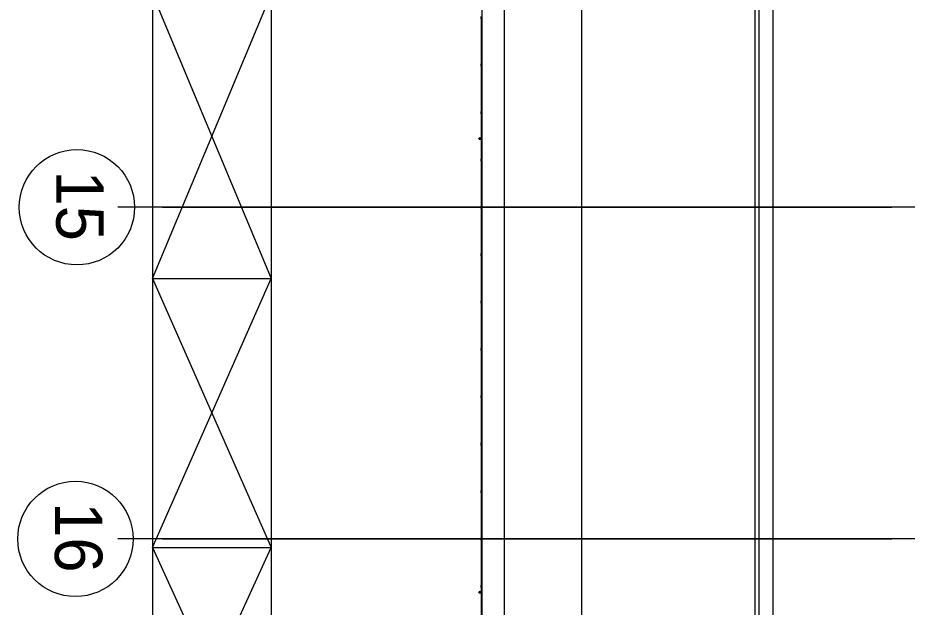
# Model space of a CAD drawing. Extents: x -264165 to -263575, y -1242333 to -1242036.
# Drawn here: x -263923.93 to -263905.18, y -1242183.32 to -1242170.88 of the extents above; entities that cross this region are included whole.
import ezdxf

# ---------------------------------------------------------------- set-up
doc = ezdxf.new("R2010")
doc.units = 0
doc.layers.add('KFA_HESCON_OSI_STAVBY', color=7, linetype='Continuous')
doc.layers.add('KFA_SITUACIA_DRS_VYTYCOVAK_SEDA', color=7, linetype='Continuous')

msp = doc.modelspace()

# ---------------------------------------------------------------- linework, layer by layer
at = {"layer": 'KFA_HESCON_OSI_STAVBY'}
for p, q in [((-263908.393, -1242080.447), (-263908.393, -1242248.737)), ((-263787.486, -1242174.882), (-263921.823, -1242174.882)), ((-263920.885, -1242174.882), (-263905.505, -1242174.882)), ((-263787.486, -1242181.882), (-263921.823, -1242181.882)), ((-263920.885, -1242181.882), (-263905.505, -1242181.882))]:
    msp.add_line(p, q, dxfattribs=at)
for centre in [(-263922.688, -1242174.882), (-263922.718, -1242181.882)]:
    msp.add_circle(centre, 1.216, dxfattribs=at)
at = {"layer": 'KFA_SITUACIA_DRS_VYTYCOVAK_SEDA'}
for p, q in [((-263921.093, -1242087.308), (-263921.093, -1242241.458)), ((-263912.043, -1242228.625), (-263912.043, -1242100.14)), ((-263914.153, -1242132.422), (-263914.153, -1242196.342)), ((-263914.153, -1242132.422), (-263914.153, -1242196.342)), ((-263914.143, -1242196.333), (-263914.143, -1242132.433)), ((-263913.683, -1242132.892), (-263913.683, -1242195.872)), ((-263913.683, -1242132.892), (-263913.683, -1242195.872)), ((-263908.308, -1242135.882), (-263908.308, -1242192.882)), ((-263908.308, -1242135.882), (-263908.308, -1242192.882)), ((-263908.008, -1242192.882), (-263908.008, -1242135.882)), ((-263908.008, -1242192.882), (-263908.008, -1242135.882)), ((-263918.593, -1242141.207), (-263918.593, -1242187.557)), ((-263921.093, -1242170.382), (-263918.593, -1242176.382)), ((-263921.093, -1242176.382), (-263918.593, -1242170.382)), ((-263914.168, -1242170.907), (-263914.168, -1242170.857)), ((-263914.168, -1242170.907), (-263914.168, -1242170.857)), ((-263914.168, -1242170.907), (-263914.168, -1242171.857)), ((-263914.168, -1242170.907), (-263914.168, -1242171.857)), ((-263914.168, -1242170.907), (-263914.168, -1242171.857)), ((-263914.168, -1242170.907), (-263914.168, -1242171.857)), ((-263914.168, -1242171.907), (-263914.168, -1242171.857)), ((-263914.168, -1242171.907), (-263914.168, -1242171.857)), ((-263914.168, -1242171.907), (-263914.168, -1242172.857)), ((-263914.168, -1242171.907), (-263914.168, -1242172.857)), ((-263914.168, -1242171.907), (-263914.168, -1242172.857)), ((-263914.168, -1242171.907), (-263914.168, -1242172.857)), ((-263914.168, -1242172.907), (-263914.168, -1242172.857)), ((-263914.168, -1242172.907), (-263914.168, -1242172.857)), ((-263914.168, -1242172.907), (-263914.168, -1242173.857)), ((-263914.168, -1242172.907), (-263914.168, -1242173.857)), ((-263914.213, -1242173.432), (-263914.21, -1242173.422)), ((-263914.213, -1242173.432), (-263914.21, -1242173.422)), ((-263914.21, -1242173.442), (-263914.213, -1242173.432)), ((-263914.21, -1242173.442), (-263914.213, -1242173.432)), ((-263914.21, -1242173.422), (-263914.203, -1242173.415)), ((-263914.21, -1242173.422), (-263914.203, -1242173.415)), ((-263914.21, -1242173.424), (-263914.21, -1242173.422)), ((-263914.21, -1242173.424), (-263914.21, -1242173.422)), ((-263914.21, -1242173.427), (-263914.21, -1242173.424)), ((-263914.21, -1242173.427), (-263914.21, -1242173.424)), ((-263914.21, -1242173.432), (-263914.21, -1242173.427)), ((-263914.21, -1242173.432), (-263914.21, -1242173.427)), ((-263914.21, -1242173.437), (-263914.21, -1242173.432)), ((-263914.21, -1242173.437), (-263914.21, -1242173.432)), ((-263914.21, -1242173.441), (-263914.21, -1242173.437)), ((-263914.21, -1242173.441), (-263914.21, -1242173.437)), ((-263914.21, -1242173.442), (-263914.21, -1242173.441)), ((-263914.21, -1242173.442), (-263914.21, -1242173.441)), ((-263914.203, -1242173.45), (-263914.21, -1242173.442)), ((-263914.203, -1242173.45), (-263914.21, -1242173.442)), ((-263914.203, -1242173.415), (-263914.193, -1242173.412)), ((-263914.203, -1242173.415), (-263914.193, -1242173.412)), ((-263914.203, -1242173.417), (-263914.203, -1242173.415)), ((-263914.203, -1242173.417), (-263914.203, -1242173.415)), ((-263914.203, -1242173.417), (-263914.193, -1242173.415)), ((-263914.203, -1242173.417), (-263914.193, -1242173.415)), ((-263914.203, -1242173.424), (-263914.203, -1242173.417)), ((-263914.203, -1242173.424), (-263914.203, -1242173.417)), ((-263914.203, -1242173.424), (-263914.193, -1242173.422)), ((-263914.203, -1242173.424), (-263914.193, -1242173.422)), ((-263914.203, -1242173.432), (-263914.203, -1242173.424)), ((-263914.203, -1242173.432), (-263914.203, -1242173.424)), ((-263914.203, -1242173.441), (-263914.203, -1242173.432)), ((-263914.203, -1242173.441), (-263914.203, -1242173.432)), ((-263914.203, -1242173.432), (-263914.193, -1242173.432)), ((-263914.203, -1242173.432), (-263914.193, -1242173.432)), ((-263914.203, -1242173.441), (-263914.193, -1242173.442)), ((-263914.203, -1242173.441), (-263914.193, -1242173.442)), ((-263914.203, -1242173.447), (-263914.203, -1242173.441)), ((-263914.203, -1242173.447), (-263914.203, -1242173.441)), ((-263914.203, -1242173.45), (-263914.203, -1242173.447)), ((-263914.203, -1242173.45), (-263914.203, -1242173.447)), ((-263914.203, -1242173.447), (-263914.193, -1242173.45)), ((-263914.203, -1242173.447), (-263914.193, -1242173.45)), ((-263914.193, -1242173.452), (-263914.203, -1242173.45)), ((-263914.193, -1242173.452), (-263914.203, -1242173.45)), ((-263914.193, -1242173.412), (-263914.183, -1242173.415)), ((-263914.193, -1242173.412), (-263914.183, -1242173.415)), ((-263914.193, -1242173.412), (-263914.193, -1242173.415)), ((-263914.193, -1242173.412), (-263914.193, -1242173.415)), ((-263914.193, -1242173.415), (-263914.183, -1242173.417)), ((-263914.193, -1242173.415), (-263914.183, -1242173.417)), ((-263914.193, -1242173.415), (-263914.193, -1242173.422)), ((-263914.193, -1242173.415), (-263914.193, -1242173.422)), ((-263914.193, -1242173.422), (-263914.193, -1242173.432)), ((-263914.193, -1242173.422), (-263914.193, -1242173.432)), ((-263914.193, -1242173.422), (-263914.183, -1242173.424)), ((-263914.193, -1242173.422), (-263914.183, -1242173.424)), ((-263914.193, -1242173.432), (-263914.193, -1242173.442)), ((-263914.193, -1242173.432), (-263914.193, -1242173.442)), ((-263914.193, -1242173.432), (-263914.183, -1242173.432)), ((-263914.193, -1242173.432), (-263914.183, -1242173.432)), ((-263914.193, -1242173.442), (-263914.183, -1242173.441)), ((-263914.193, -1242173.442), (-263914.183, -1242173.441)), ((-263914.193, -1242173.442), (-263914.193, -1242173.45)), ((-263914.193, -1242173.442), (-263914.193, -1242173.45)), ((-263914.193, -1242173.45), (-263914.183, -1242173.447)), ((-263914.193, -1242173.45), (-263914.183, -1242173.447)), ((-263914.193, -1242173.45), (-263914.193, -1242173.452)), ((-263914.193, -1242173.45), (-263914.193, -1242173.452)), ((-263914.183, -1242173.45), (-263914.193, -1242173.452)), ((-263914.183, -1242173.45), (-263914.193, -1242173.452)), ((-263914.183, -1242173.415), (-263914.176, -1242173.422)), ((-263914.183, -1242173.415), (-263914.176, -1242173.422)), ((-263914.183, -1242173.415), (-263914.183, -1242173.417)), ((-263914.183, -1242173.415), (-263914.183, -1242173.417)), ((-263914.183, -1242173.417), (-263914.183, -1242173.424)), ((-263914.183, -1242173.417), (-263914.183, -1242173.424)), ((-263914.183, -1242173.424), (-263914.183, -1242173.432)), ((-263914.183, -1242173.424), (-263914.183, -1242173.432)), ((-263914.183, -1242173.432), (-263914.183, -1242173.441)), ((-263914.183, -1242173.432), (-263914.183, -1242173.441)), ((-263914.183, -1242173.441), (-263914.183, -1242173.447)), ((-263914.183, -1242173.441), (-263914.183, -1242173.447)), ((-263914.176, -1242173.442), (-263914.183, -1242173.45)), ((-263914.176, -1242173.442), (-263914.183, -1242173.45)), ((-263914.183, -1242173.447), (-263914.183, -1242173.45)), ((-263914.183, -1242173.447), (-263914.183, -1242173.45)), ((-263914.176, -1242173.422), (-263914.168, -1242173.422)), ((-263914.176, -1242173.422), (-263914.168, -1242173.422)), ((-263914.176, -1242173.422), (-263914.176, -1242173.424)), ((-263914.176, -1242173.422), (-263914.176, -1242173.424)), ((-263914.176, -1242173.424), (-263914.168, -1242173.424)), ((-263914.176, -1242173.424), (-263914.168, -1242173.424)), ((-263914.176, -1242173.424), (-263914.176, -1242173.427)), ((-263914.176, -1242173.424), (-263914.176, -1242173.427)), ((-263914.176, -1242173.427), (-263914.168, -1242173.427)), ((-263914.176, -1242173.427), (-263914.168, -1242173.427)), ((-263914.176, -1242173.427), (-263914.176, -1242173.432)), ((-263914.176, -1242173.427), (-263914.176, -1242173.432)), ((-263914.176, -1242173.432), (-263914.168, -1242173.432)), ((-263914.176, -1242173.432), (-263914.168, -1242173.432)), ((-263914.176, -1242173.432), (-263914.176, -1242173.437)), ((-263914.176, -1242173.432), (-263914.176, -1242173.437)), ((-263914.176, -1242173.437), (-263914.168, -1242173.437)), ((-263914.176, -1242173.437), (-263914.168, -1242173.437)), ((-263914.176, -1242173.437), (-263914.176, -1242173.441)), ((-263914.176, -1242173.437), (-263914.176, -1242173.441)), ((-263914.176, -1242173.441), (-263914.168, -1242173.441)), ((-263914.176, -1242173.441), (-263914.168, -1242173.441)), ((-263914.176, -1242173.441), (-263914.176, -1242173.442)), ((-263914.176, -1242173.441), (-263914.176, -1242173.442)), ((-263914.176, -1242173.442), (-263914.168, -1242173.442)), ((-263914.176, -1242173.442), (-263914.168, -1242173.442)), ((-263914.168, -1242173.907), (-263914.168, -1242173.857)), ((-263914.168, -1242173.907), (-263914.168, -1242173.857)), ((-263914.168, -1242173.907), (-263914.168, -1242174.857)), ((-263914.168, -1242173.907), (-263914.168, -1242174.857)), ((-263914.168, -1242174.907), (-263914.168, -1242174.857)), ((-263914.168, -1242174.907), (-263914.168, -1242174.857)), ((-263914.168, -1242174.907), (-263914.168, -1242175.857)), ((-263914.168, -1242174.907), (-263914.168, -1242175.857)), ((-263914.168, -1242174.907), (-263914.168, -1242175.857)), ((-263914.168, -1242174.907), (-263914.168, -1242175.857)), ((-263914.168, -1242175.907), (-263914.168, -1242175.857)), ((-263914.168, -1242175.907), (-263914.168, -1242175.857)), ((-263914.168, -1242175.907), (-263914.168, -1242176.857)), ((-263914.168, -1242175.907), (-263914.168, -1242176.857)), ((-263914.168, -1242175.907), (-263914.168, -1242176.857)), ((-263914.168, -1242175.907), (-263914.168, -1242176.857)), ((-263921.093, -1242176.382), (-263918.593, -1242176.382)), ((-263921.093, -1242176.382), (-263918.593, -1242182.062)), ((-263921.093, -1242182.062), (-263918.593, -1242176.382)), ((-263914.168, -1242176.907), (-263914.168, -1242176.857)), ((-263914.168, -1242176.907), (-263914.168, -1242176.857)), ((-263914.168, -1242176.907), (-263914.168, -1242177.857)), ((-263914.168, -1242176.907), (-263914.168, -1242177.857)), ((-263914.168, -1242177.907), (-263914.168, -1242177.857)), ((-263914.168, -1242177.907), (-263914.168, -1242177.857)), ((-263914.168, -1242177.907), (-263914.168, -1242178.857)), ((-263914.168, -1242177.907), (-263914.168, -1242178.857)), ((-263914.168, -1242178.907), (-263914.168, -1242178.857)), ((-263914.168, -1242178.907), (-263914.168, -1242178.857)), ((-263914.168, -1242178.907), (-263914.168, -1242179.857)), ((-263914.168, -1242178.907), (-263914.168, -1242179.857)), ((-263914.168, -1242179.907), (-263914.168, -1242179.857)), ((-263914.168, -1242179.907), (-263914.168, -1242179.857)), ((-263914.168, -1242179.907), (-263914.168, -1242180.857)), ((-263914.168, -1242179.907), (-263914.168, -1242180.857)), ((-263914.168, -1242180.907), (-263914.168, -1242180.857)), ((-263914.168, -1242180.907), (-263914.168, -1242180.857)), ((-263914.168, -1242180.907), (-263914.168, -1242181.857)), ((-263914.168, -1242180.907), (-263914.168, -1242181.857)), ((-263914.168, -1242181.907), (-263914.168, -1242181.857)), ((-263914.168, -1242181.907), (-263914.168, -1242181.857)), ((-263914.168, -1242181.907), (-263914.168, -1242182.857)), ((-263914.168, -1242181.907), (-263914.168, -1242182.857)), ((-263921.093, -1242182.062), (-263918.593, -1242182.062)), ((-263921.093, -1242182.062), (-263918.593, -1242187.557)), ((-263921.093, -1242187.557), (-263918.593, -1242182.062)), ((-263914.168, -1242182.907), (-263914.168, -1242182.857)), ((-263914.168, -1242182.907), (-263914.168, -1242182.857)), ((-263914.213, -1242183.007), (-263914.21, -1242182.997)), ((-263914.213, -1242183.007), (-263914.21, -1242182.997)), ((-263914.21, -1242183.017), (-263914.213, -1242183.007)), ((-263914.21, -1242183.017), (-263914.213, -1242183.007)), ((-263914.21, -1242182.997), (-263914.203, -1242182.989)), ((-263914.21, -1242182.997), (-263914.203, -1242182.989)), ((-263914.21, -1242182.998), (-263914.21, -1242182.997)), ((-263914.21, -1242182.998), (-263914.21, -1242182.997)), ((-263914.21, -1242183.002), (-263914.21, -1242182.998)), ((-263914.21, -1242183.002), (-263914.21, -1242182.998)), ((-263914.21, -1242183.007), (-263914.21, -1242183.002)), ((-263914.21, -1242183.007), (-263914.21, -1242183.002)), ((-263914.21, -1242183.012), (-263914.21, -1242183.007)), ((-263914.21, -1242183.012), (-263914.21, -1242183.007)), ((-263914.21, -1242183.015), (-263914.21, -1242183.012)), ((-263914.21, -1242183.015), (-263914.21, -1242183.012)), ((-263914.21, -1242183.017), (-263914.21, -1242183.015)), ((-263914.21, -1242183.017), (-263914.21, -1242183.015)), ((-263914.203, -1242183.024), (-263914.21, -1242183.017)), ((-263914.203, -1242183.024), (-263914.21, -1242183.017)), ((-263914.203, -1242182.989), (-263914.193, -1242182.987)), ((-263914.203, -1242182.989), (-263914.193, -1242182.987)), ((-263914.203, -1242182.992), (-263914.203, -1242182.989)), ((-263914.203, -1242182.992), (-263914.203, -1242182.989)), ((-263914.203, -1242182.992), (-263914.193, -1242182.989)), ((-263914.203, -1242182.992), (-263914.193, -1242182.989)), ((-263914.203, -1242182.998), (-263914.203, -1242182.992)), ((-263914.203, -1242182.998), (-263914.203, -1242182.992)), ((-263914.203, -1242182.998), (-263914.193, -1242182.997)), ((-263914.203, -1242182.998), (-263914.193, -1242182.997)), ((-263914.203, -1242183.007), (-263914.203, -1242182.998)), ((-263914.203, -1242183.007), (-263914.203, -1242182.998)), ((-263914.203, -1242183.015), (-263914.203, -1242183.007)), ((-263914.203, -1242183.015), (-263914.203, -1242183.007)), ((-263914.203, -1242183.007), (-263914.193, -1242183.007)), ((-263914.203, -1242183.007), (-263914.193, -1242183.007)), ((-263914.203, -1242183.015), (-263914.193, -1242183.017)), ((-263914.203, -1242183.015), (-263914.193, -1242183.017)), ((-263914.203, -1242183.022), (-263914.203, -1242183.015)), ((-263914.203, -1242183.022), (-263914.203, -1242183.015)), ((-263914.203, -1242183.024), (-263914.203, -1242183.022)), ((-263914.203, -1242183.024), (-263914.203, -1242183.022)), ((-263914.203, -1242183.022), (-263914.193, -1242183.024)), ((-263914.203, -1242183.022), (-263914.193, -1242183.024)), ((-263914.193, -1242183.027), (-263914.203, -1242183.024)), ((-263914.193, -1242183.027), (-263914.203, -1242183.024)), ((-263914.193, -1242182.987), (-263914.183, -1242182.989)), ((-263914.193, -1242182.987), (-263914.183, -1242182.989)), ((-263914.193, -1242182.987), (-263914.193, -1242182.989)), ((-263914.193, -1242182.987), (-263914.193, -1242182.989)), ((-263914.193, -1242182.989), (-263914.183, -1242182.992)), ((-263914.193, -1242182.989), (-263914.183, -1242182.992)), ((-263914.193, -1242182.989), (-263914.193, -1242182.997)), ((-263914.193, -1242182.989), (-263914.193, -1242182.997)), ((-263914.193, -1242182.997), (-263914.193, -1242183.007)), ((-263914.193, -1242182.997), (-263914.193, -1242183.007)), ((-263914.193, -1242182.997), (-263914.183, -1242182.998)), ((-263914.193, -1242182.997), (-263914.183, -1242182.998)), ((-263914.193, -1242183.007), (-263914.193, -1242183.017)), ((-263914.193, -1242183.007), (-263914.193, -1242183.017)), ((-263914.193, -1242183.007), (-263914.183, -1242183.007)), ((-263914.193, -1242183.007), (-263914.183, -1242183.007)), ((-263914.193, -1242183.017), (-263914.183, -1242183.015)), ((-263914.193, -1242183.017), (-263914.183, -1242183.015)), ((-263914.193, -1242183.017), (-263914.193, -1242183.024)), ((-263914.193, -1242183.017), (-263914.193, -1242183.024)), ((-263914.193, -1242183.024), (-263914.183, -1242183.022)), ((-263914.193, -1242183.024), (-263914.183, -1242183.022)), ((-263914.193, -1242183.024), (-263914.193, -1242183.027)), ((-263914.193, -1242183.024), (-263914.193, -1242183.027)), ((-263914.183, -1242183.024), (-263914.193, -1242183.027)), ((-263914.183, -1242183.024), (-263914.193, -1242183.027)), ((-263914.183, -1242182.989), (-263914.176, -1242182.997)), ((-263914.183, -1242182.989), (-263914.176, -1242182.997)), ((-263914.183, -1242182.989), (-263914.183, -1242182.992)), ((-263914.183, -1242182.989), (-263914.183, -1242182.992)), ((-263914.183, -1242182.992), (-263914.183, -1242182.998)), ((-263914.183, -1242182.992), (-263914.183, -1242182.998)), ((-263914.183, -1242182.998), (-263914.183, -1242183.007)), ((-263914.183, -1242182.998), (-263914.183, -1242183.007)), ((-263914.183, -1242183.007), (-263914.183, -1242183.015)), ((-263914.183, -1242183.007), (-263914.183, -1242183.015)), ((-263914.183, -1242183.015), (-263914.183, -1242183.022)), ((-263914.183, -1242183.015), (-263914.183, -1242183.022)), ((-263914.176, -1242183.017), (-263914.183, -1242183.024)), ((-263914.176, -1242183.017), (-263914.183, -1242183.024)), ((-263914.183, -1242183.022), (-263914.183, -1242183.024)), ((-263914.183, -1242183.022), (-263914.183, -1242183.024)), ((-263914.176, -1242182.997), (-263914.168, -1242182.997)), ((-263914.176, -1242182.997), (-263914.168, -1242182.997)), ((-263914.176, -1242182.997), (-263914.176, -1242182.998)), ((-263914.176, -1242182.997), (-263914.176, -1242182.998)), ((-263914.176, -1242182.998), (-263914.168, -1242182.998)), ((-263914.176, -1242182.998), (-263914.168, -1242182.998)), ((-263914.176, -1242182.998), (-263914.176, -1242183.002)), ((-263914.176, -1242182.998), (-263914.176, -1242183.002)), ((-263914.176, -1242183.002), (-263914.168, -1242183.002)), ((-263914.176, -1242183.002), (-263914.168, -1242183.002)), ((-263914.176, -1242183.002), (-263914.176, -1242183.007)), ((-263914.176, -1242183.002), (-263914.176, -1242183.007)), ((-263914.176, -1242183.007), (-263914.168, -1242183.007)), ((-263914.176, -1242183.007), (-263914.168, -1242183.007)), ((-263914.176, -1242183.007), (-263914.176, -1242183.012)), ((-263914.176, -1242183.007), (-263914.176, -1242183.012)), ((-263914.176, -1242183.012), (-263914.168, -1242183.012)), ((-263914.176, -1242183.012), (-263914.168, -1242183.012)), ((-263914.176, -1242183.012), (-263914.176, -1242183.015)), ((-263914.176, -1242183.012), (-263914.176, -1242183.015)), ((-263914.176, -1242183.015), (-263914.168, -1242183.015)), ((-263914.176, -1242183.015), (-263914.168, -1242183.015)), ((-263914.176, -1242183.015), (-263914.176, -1242183.017)), ((-263914.176, -1242183.015), (-263914.176, -1242183.017)), ((-263914.176, -1242183.017), (-263914.168, -1242183.017)), ((-263914.176, -1242183.017), (-263914.168, -1242183.017)), ((-263914.168, -1242182.907), (-263914.168, -1242183.857)), ((-263914.168, -1242182.907), (-263914.168, -1242183.857))]:
    msp.add_line(p, q, dxfattribs=at)

# ---------------------------------------------------------------- texts
at = {"layer": 'KFA_HESCON_OSI_STAVBY'}
for s, p in [('15', (-263923.123, -1242174.105)), ('16', (-263923.153, -1242181.105))]:
    msp.add_text(s, height=1, rotation=270, dxfattribs=at).set_placement(p)

doc.saveas('drawing.dxf')
